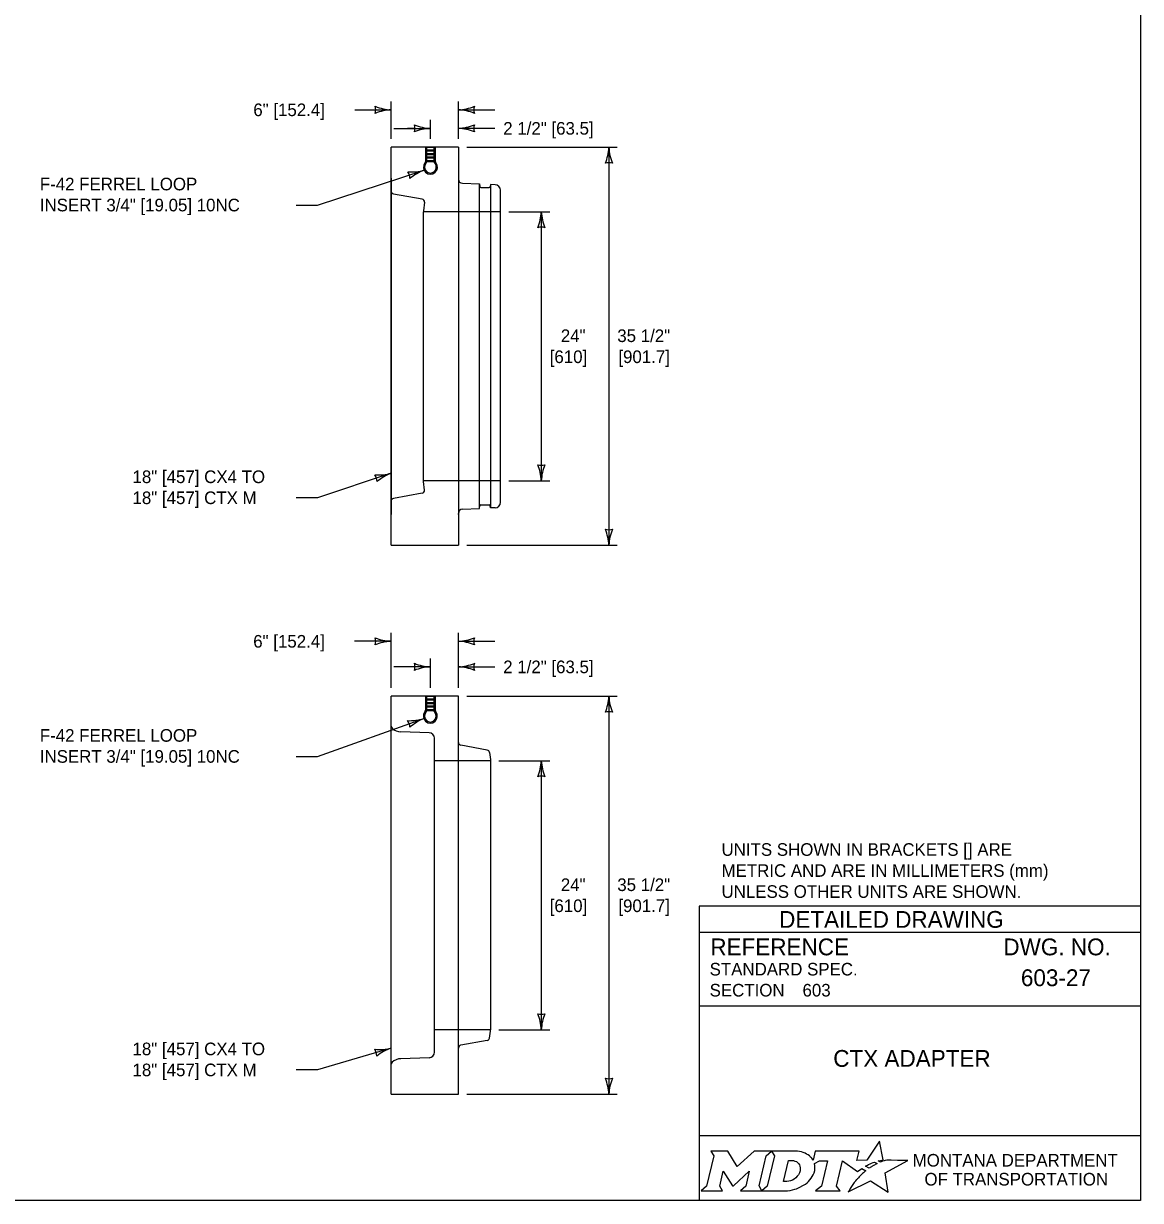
# Model space of a CAD drawing. Extents: x 49991.4 to 50021, y 49987.6 to 50011.4.
# Drawn here: x 50011.44 to 50016.75, y 49987.8 to 49993.4 of the extents above; entities that cross this region are included whole.
import ezdxf

# ---------------------------------------------------------------- set-up
doc = ezdxf.new("R2010")
doc.units = 0
for name, color, linetype in [('CONCRETE', 7, 'Continuous'), ('Default', 7, 'Continuous'), ('Level 1', 7, 'Continuous'), ('Level 2', 7, 'Continuous'), ('Level 25', 7, 'Continuous'), ('Level 3', 7, 'Continuous'), ('Level 4', 7, 'Continuous'), ('Level 5', 7, 'Continuous'), ('TEXT', 7, 'Continuous')]:
    doc.layers.add(name, color=color, linetype=linetype)

msp = doc.modelspace()

# ---------------------------------------------------------------- linework, layer by layer
at = {"layer": 'CONCRETE'}
for p, q in [((50013.1852, 49992.6637), (50013.1852, 49992.6013)), ((50013.5052, 49992.6637), (50013.5052, 49992.659)), ((50013.1852, 49991.0637), (50013.1852, 49991.1262))]:
    msp.add_line(p, q, dxfattribs=at)
at = {"layer": 'Default'}
for points in [[(50015.5126, 49987.9811), (50015.5023, 49987.9867), (50015.5139, 49987.9895), (50015.5255, 49987.9915), (50015.5081, 49988.0816), (50015.4486, 49987.9903), (50015.4013, 49987.9896), (50015.4116, 49988.0337), (50015.2024, 49988.0338), (50015.1923, 49987.9913), (50015.1865, 49987.9996)], [(50014.7056, 49988.0338), (50014.7197, 49988.0104), (50014.6862, 49987.8671), (50014.6605, 49987.8446), (50014.7621, 49987.8446), (50014.7486, 49987.8674), (50014.7648, 49987.9375), (50014.8085, 49987.8685), (50014.8138, 49987.8685), (50014.8889, 49987.938), (50014.8725, 49987.8669), (50014.8478, 49987.8449), (50014.9494, 49987.8449), (50014.9356, 49987.8682), (50014.9688, 49988.0106)], [(50014.9688, 49988.0106), (50014.9941, 49988.0338), (50014.9117, 49988.0338), (50014.8321, 49987.9608), (50014.7876, 49988.0335), (50014.7056, 49988.0338)], [(50015.1077, 49988.0338), (50014.9941, 49988.0338), (50015.0088, 49988.0109), (50014.9749, 49987.8671), (50014.9494, 49987.8449), (50015.06, 49987.8449)], [(50015.1317, 49987.9471), (50015.1305, 49987.939), (50015.1273, 49987.9297), (50015.1231, 49987.9215), (50015.1175, 49987.914), (50015.111, 49987.9071), (50015.1031, 49987.9008), (50015.0948, 49987.8961), (50015.0857, 49987.8922), (50015.0766, 49987.8899), (50015.0674, 49987.889), (50015.0515, 49987.889), (50015.0751, 49987.989), (50015.0911, 49987.989), (50015.0987, 49987.9884), (50015.1063, 49987.9865), (50015.1129, 49987.9835), (50015.119, 49987.9793), (50015.1238, 49987.9743), (50015.1275, 49987.9683), (50015.1302, 49987.9621), (50015.1318, 49987.9547), (50015.1318, 49987.9517), (50015.1317, 49987.9471)], [(50015.1991, 49987.9747), (50015.2237, 49987.9878), (50015.2606, 49987.9878), (50015.232, 49987.8673), (50015.2045, 49987.8446), (50015.3207, 49987.8446), (50015.3037, 49987.8675), (50015.3319, 49987.9877), (50015.4032, 49987.936), (50015.4243, 49987.9511), (50015.444, 49987.9402)], [(50015.3882, 49987.8843), (50015.3729, 49987.8599), (50015.3682, 49987.8524), (50015.3624, 49987.8438), (50015.3601, 49987.8395), (50015.4654, 49987.8926), (50015.5493, 49987.8375), (50015.5362, 49987.9302), (50015.6431, 49987.9886), (50015.5938, 49987.9894), (50015.5637, 49987.9898), (50015.5429, 49987.9901), (50015.5361, 49987.9886), (50015.5312, 49987.9874), (50015.5228, 49987.9851), (50015.5126, 49987.9811)], [(50015.4622, 49987.9535), (50015.4598, 49987.9518), (50015.4415, 49987.9614), (50015.4518, 49987.9671), (50015.4559, 49987.9693), (50015.4645, 49987.9733), (50015.4702, 49987.9759), (50015.4781, 49987.9789), (50015.4854, 49987.9816), (50015.4972, 49987.9742), (50015.4932, 49987.9721), (50015.4886, 49987.9696), (50015.4844, 49987.9674), (50015.4794, 49987.9645), (50015.4775, 49987.9634), (50015.4748, 49987.9618), (50015.4723, 49987.9604), (50015.47, 49987.9588), (50015.4674, 49987.957), (50015.4647, 49987.9552), (50015.4622, 49987.9535)], [(50015.1057, 49987.8522), (50015.1141, 49987.8548), (50015.1271, 49987.8602), (50015.1475, 49987.8712)], [(50015.4021, 49987.9004), (50015.4021, 49987.9004)]]:
    msp.add_lwpolyline(points, dxfattribs=at)
for centre, radius, start, end in [((50015.0868, 49987.9727), 0.1183, 300.9103, 339.1383), ((50015.1308, 49987.9554), 0.0709, 339.5329, 15.8582)]:
    msp.add_arc(centre, radius, start, end, dxfattribs=at)
for centre, major_axis, ratio, start_param, end_param in [((50015.1056, 49987.9864), (0.0834, -0.0037), 0.568097, 0.61298, 1.570796), ((50015.1612, 49987.9937), (0.0361, -0.0295), 0.469099, 1.225588, 1.570796), ((50015.4329, 49987.9305), (-0.0112, -0.0097), 0.021651, 3.157348, 6.283185), ((50015.3952, 49987.8923), (-0.00694, -0.00806), 0.008222, 0, 3.137361), ((50015.4119, 49987.9106), (-0.0098, -0.0102), 0.016458, 3.141593, 6.279097), ((50015.0603, 49987.9932), (0, 0.1484), 0.987302, 3.139398, 3.456847)]:
    msp.add_ellipse(centre, major_axis=major_axis, ratio=ratio, start_param=start_param, end_param=end_param, dxfattribs=at)
at = {"layer": 'Level 1'}
for p, q in [((50013.1852, 49990.9171), (50013.1852, 49992.8104)), ((50013.5052, 49992.8104), (50013.1852, 49992.8104)), ((50013.5052, 49992.8104), (50013.5052, 49990.9171)), ((50013.1852, 49992.6637), (50013.1852, 49991.0637)), ((50013.5246, 49992.639), (50013.605, 49992.6365)), ((50013.605, 49991.091), (50013.605, 49992.6365)), ((50013.605, 49992.6365), (50013.6073, 49992.6231)), ((50013.6583, 49992.6333), (50013.6565, 49992.6231)), ((50013.6583, 49992.6333), (50013.6583, 49991.0942)), ((50013.6794, 49992.6326), (50013.6583, 49992.6333)), ((50013.6122, 49992.619), (50013.6516, 49992.619)), ((50013.7052, 49991.1215), (50013.7052, 49992.6059)), ((50013.5052, 49991.0637), (50013.5052, 49991.0684)), ((50013.5246, 49991.0884), (50013.605, 49991.091)), ((50013.605, 49991.091), (50013.6073, 49991.1043)), ((50013.6122, 49991.1085), (50013.6516, 49991.1085)), ((50013.6583, 49991.0942), (50013.6565, 49991.1043)), ((50013.6794, 49991.0949), (50013.6583, 49991.0942)), ((50013.1852, 49990.9171), (50013.5052, 49990.9171)), ((50013.1849, 49988.3045), (50013.1849, 49990.1978)), ((50013.5049, 49990.1978), (50013.1849, 49990.1978)), ((50013.5049, 49988.3045), (50013.5049, 49990.1978)), ((50013.6422, 49989.9421), (50013.5159, 49989.9649)), ((50013.653, 49989.931), (50013.6582, 49989.8978)), ((50013.6582, 49989.8978), (50013.6582, 49989.8912)), ((50013.6582, 49989.8912), (50013.6582, 49988.6112)), ((50013.653, 49988.5713), (50013.6582, 49988.6045)), ((50013.6582, 49988.6045), (50013.6582, 49988.6112)), ((50013.6422, 49988.5603), (50013.5159, 49988.5374)), ((50013.1849, 49988.3045), (50013.5049, 49988.3045))]:
    msp.add_line(p, q, dxfattribs=at)
msp.add_lwpolyline([(49999.3835, 49998.9992), (50016.7501, 49998.9992), (50016.7501, 49987.7988), (49999.3835, 49987.7988)], close=True, dxfattribs=at)
for centre, radius, start, end in [((50013.5252, 49992.659), 0.02, 180, 268.167), ((50013.6785, 49992.6059), 0.0267, 0, 88.167), ((50013.6122, 49992.624), 0.005, 190, 270), ((50013.6516, 49992.624), 0.005, 270, 350), ((50013.6785, 49991.1215), 0.0267, 271.833, 0), ((50013.5252, 49991.0684), 0.02, 91.833, 180), ((50013.6122, 49991.1035), 0.005, 90, 170), ((50013.6516, 49991.1035), 0.005, 10, 90), ((50013.5182, 49989.978), 0.0133, 180, 259.7456), ((50013.6399, 49989.9289), 0.0133, 8.9081, 79.7456), ((50013.6399, 49988.5734), 0.0133, 280.2544, 351.0919), ((50013.5182, 49988.5243), 0.0133, 100.2544, 180)]:
    msp.add_arc(centre, radius, start, end, dxfattribs=at)
at = {"layer": 'Level 3'}
for p, q in [((50013.1852, 49992.8504), (50013.1852, 49993.0288)), ((50013.5052, 49992.8504), (50013.5052, 49993.0288)), ((50013.0118, 49992.9888), (50013.1852, 49992.9888)), ((50013.5052, 49992.9888), (50013.6786, 49992.9888)), ((50013.3719, 49992.8504), (50013.3719, 49992.9406)), ((50013.5052, 49992.8504), (50013.5052, 49992.9406)), ((50013.1984, 49992.9006), (50013.3719, 49992.9006)), ((50013.2984, 49992.9006), (50013.2637, 49992.9006)), ((50013.6786, 49992.9006), (50013.5052, 49992.9006)), ((50013.3552, 49992.8104), (50013.3885, 49992.8104)), ((50013.5452, 49992.8104), (50014.2611, 49992.8104)), ((50014.2211, 49992.8104), (50014.2211, 49990.9171)), ((50013.7452, 49992.5037), (50013.9396, 49992.5037)), ((50013.8996, 49992.5037), (50013.8996, 49991.2237)), ((50013.7452, 49991.2237), (50013.9396, 49991.2237)), ((50013.5452, 49990.9171), (50014.2611, 49990.9171)), ((50013.1849, 49990.2378), (50013.1849, 49990.4996)), ((50013.5049, 49990.2378), (50013.5049, 49990.4996)), ((50013.1849, 49990.4596), (50013.0115, 49990.4596)), ((50013.5049, 49990.4596), (50013.6783, 49990.4596)), ((50013.3716, 49990.338), (50013.1981, 49990.338)), ((50013.3716, 49990.2378), (50013.3716, 49990.378)), ((50013.5049, 49990.2378), (50013.5049, 49990.378)), ((50013.5049, 49990.338), (50013.6783, 49990.338)), ((50013.5449, 49990.1978), (50014.2611, 49990.1978)), ((50014.2211, 49990.1978), (50014.2211, 49988.3045)), ((50013.6982, 49989.8912), (50013.9396, 49989.8912)), ((50013.8996, 49989.8912), (50013.8996, 49988.6112)), ((50013.6982, 49988.6112), (50013.9396, 49988.6112)), ((50013.5449, 49988.3045), (50014.2611, 49988.3045))]:
    msp.add_line(p, q, dxfattribs=at)
for points in [[(50012.734, 49992.5356), (50012.834, 49992.5356), (50013.3419, 49992.7014)], [(50013.1852, 49991.2597), (50012.834, 49991.1426), (50012.734, 49991.1426)], [(50012.734, 49989.9118), (50012.834, 49989.9118), (50013.3403, 49990.0918)], [(50013.1849, 49988.5235), (50012.834, 49988.42), (50012.734, 49988.42)]]:
    msp.add_lwpolyline(points, dxfattribs=at)
for centre, radius, start, end in [((50013.1944, 49993.2109), 0.2223, 247.4389, 267.6225), ((50013.057, 49992.9888), 0.0548, 342.1218, 17.8441), ((50013.1966, 49992.7561), 0.233, 92.8102, 112.0601), ((50013.4938, 49993.2215), 0.233, 272.8102, 292.0601), ((50013.496, 49992.7667), 0.2223, 67.4389, 87.6225), ((50013.6334, 49992.9888), 0.0548, 162.1218, 197.8441), ((50013.3811, 49993.1227), 0.2223, 247.4389, 267.6225), ((50013.2437, 49992.9006), 0.0548, 342.1218, 17.8441), ((50013.4938, 49993.1333), 0.233, 272.8102, 292.0601), ((50013.6334, 49992.9005), 0.0548, 162.1218, 197.8441), ((50013.3833, 49992.6678), 0.233, 92.8102, 112.0601), ((50013.496, 49992.6784), 0.2223, 67.4389, 87.6225), ((50013.9989, 49992.8196), 0.2223, 337.4389, 357.6225), ((50014.4538, 49992.8218), 0.233, 182.8102, 202.0601), ((50013.2816, 49992.9154), 0.2223, 265.5377, 285.7212), ((50013.22, 49992.6616), 0.0548, 0.2205, 35.9429), ((50013.425, 49992.4837), 0.233, 110.909, 130.1588), ((50014.221, 49992.6822), 0.0548, 72.1218, 107.8441), ((50013.6775, 49992.513), 0.2223, 337.4389, 357.6225), ((50014.1323, 49992.5152), 0.233, 182.8102, 202.0601), ((50013.8995, 49992.3755), 0.0548, 72.1218, 107.8441), ((50013.8996, 49991.3519), 0.0548, 252.1218, 287.8441), ((50013.6669, 49991.2123), 0.233, 2.8102, 22.0601), ((50014.1217, 49991.2145), 0.2223, 157.4389, 177.6225), ((50013.1236, 49991.4733), 0.2223, 265.908, 286.0916), ((50013.0636, 49991.2191), 0.0548, 0.5909, 36.3132), ((50013.2698, 49991.0425), 0.233, 111.2793, 130.5292), ((50014.2211, 49991.0453), 0.0548, 252.1218, 287.8441), ((50013.9884, 49990.9057), 0.233, 2.8102, 22.0601), ((50014.4432, 49990.9079), 0.2223, 157.4389, 177.6225), ((50013.1941, 49990.6818), 0.2223, 247.4389, 267.6225), ((50013.0567, 49990.4597), 0.0548, 342.1218, 17.8441), ((50013.1963, 49990.2269), 0.233, 92.8102, 112.0601), ((50013.4935, 49990.6923), 0.233, 272.8102, 292.0601), ((50013.4957, 49990.2375), 0.2223, 67.4389, 87.6225), ((50013.6331, 49990.4596), 0.0548, 162.1218, 197.8441), ((50013.3808, 49990.5602), 0.2223, 247.4389, 267.6225), ((50013.2434, 49990.3381), 0.0548, 342.1218, 17.8441), ((50013.383, 49990.1053), 0.233, 92.8102, 112.0601), ((50013.4935, 49990.5707), 0.233, 272.8102, 292.0601), ((50013.4957, 49990.1159), 0.2223, 67.4389, 87.6225), ((50013.6331, 49990.338), 0.0548, 162.1218, 197.8441), ((50013.9989, 49990.207), 0.2223, 337.4389, 357.6225), ((50014.4538, 49990.2092), 0.233, 182.8102, 202.0601), ((50014.221, 49990.0696), 0.0548, 72.1218, 107.8441), ((50013.2745, 49990.3042), 0.2223, 267.0303, 287.2139), ((50013.2195, 49990.0489), 0.0548, 1.7132, 37.4355), ((50013.4291, 49989.8764), 0.233, 112.4016, 131.6515), ((50013.6775, 49989.9004), 0.2223, 337.4389, 357.6225), ((50014.1323, 49989.9026), 0.233, 182.8102, 202.0601), ((50013.8995, 49989.763), 0.0548, 72.1218, 107.8441), ((50013.8996, 49988.7394), 0.0548, 252.1218, 287.8441), ((50013.6669, 49988.5998), 0.233, 2.8102, 22.0601), ((50014.1217, 49988.602), 0.2223, 157.4389, 177.6225), ((50013.1309, 49988.7391), 0.2223, 263.883, 284.0665), ((50013.0619, 49988.4872), 0.0548, 358.5658, 34.2882), ((50013.2617, 49988.3035), 0.233, 109.2543, 128.5041), ((50014.2211, 49988.4327), 0.0548, 252.1218, 287.8441), ((50013.9884, 49988.2931), 0.233, 2.8102, 22.0601), ((50014.4432, 49988.2953), 0.2223, 157.4389, 177.6225)]:
    msp.add_arc(centre, radius, start, end, dxfattribs=at)
at = {"layer": 'Level 4'}
for p, q in [((50013.3497, 49992.748), (50013.3497, 49992.8104)), ((50013.3552, 49992.748), (50013.3552, 49992.8104)), ((50013.3552, 49992.7983), (50013.3885, 49992.7983)), ((50013.3885, 49992.8104), (50013.3885, 49992.748)), ((50013.3941, 49992.8104), (50013.3941, 49992.748)), ((50013.348, 49992.7405), (50013.3485, 49992.7418)), ((50013.3531, 49992.7385), (50013.3536, 49992.7397)), ((50013.3547, 49992.7433), (50013.389, 49992.7433)), ((50013.3552, 49992.7936), (50013.3885, 49992.7936)), ((50013.3552, 49992.7815), (50013.3885, 49992.7815)), ((50013.3552, 49992.7768), (50013.3885, 49992.7768)), ((50013.3552, 49992.7648), (50013.3885, 49992.7648)), ((50013.3552, 49992.7601), (50013.3885, 49992.7601)), ((50013.3552, 49992.748), (50013.3885, 49992.748)), ((50013.3906, 49992.7385), (50013.3901, 49992.7397)), ((50013.3958, 49992.7405), (50013.3953, 49992.7418)), ((50013.3328, 49992.5634), (50013.1962, 49992.5882)), ((50013.3436, 49992.5487), (50013.3385, 49992.5079)), ((50013.3385, 49992.5079), (50013.3385, 49992.5037)), ((50013.3385, 49991.2237), (50013.3385, 49992.5037)), ((50013.7052, 49992.5037), (50013.3385, 49992.5037)), ((50013.3385, 49991.2196), (50013.3385, 49991.2237)), ((50013.7052, 49991.2237), (50013.3385, 49991.2237)), ((50013.3436, 49991.1788), (50013.3385, 49991.2196)), ((50013.3328, 49991.164), (50013.1962, 49991.1393)), ((50013.3494, 49990.1354), (50013.3494, 49990.1978)), ((50013.3549, 49990.1354), (50013.3549, 49990.1978)), ((50013.3549, 49990.1857), (50013.3882, 49990.1857)), ((50013.3549, 49990.181), (50013.3882, 49990.181)), ((50013.3549, 49990.169), (50013.3882, 49990.169)), ((50013.3549, 49990.1643), (50013.3882, 49990.1643)), ((50013.3882, 49990.1978), (50013.3882, 49990.1354)), ((50013.3938, 49990.1978), (50013.3938, 49990.1354)), ((50013.3477, 49990.128), (50013.3482, 49990.1292)), ((50013.3528, 49990.1259), (50013.3533, 49990.1272)), ((50013.3544, 49990.1307), (50013.3887, 49990.1307)), ((50013.3549, 49990.1522), (50013.3882, 49990.1522)), ((50013.3549, 49990.1475), (50013.3882, 49990.1475)), ((50013.3549, 49990.1354), (50013.3882, 49990.1354)), ((50013.3903, 49990.1259), (50013.3898, 49990.1272)), ((50013.3955, 49990.128), (50013.395, 49990.1292)), ((50013.3658, 49990.0246), (50013.2316, 49990.0289)), ((50013.3916, 49988.5044), (50013.3916, 49989.998)), ((50013.6582, 49989.8912), (50013.3916, 49989.8912)), ((50013.6582, 49988.6112), (50013.3916, 49988.6112)), ((50013.3658, 49988.4777), (50013.2316, 49988.4734))]:
    msp.add_line(p, q, dxfattribs=at)
for centre, radius, start, end in [((50013.3325, 49992.7467), 0.0167, 321.9927, 338.1986), ((50013.333, 49992.748), 0.0167, 338.1986, 0), ((50013.333, 49992.748), 0.0222, 338.1986, 0), ((50013.4108, 49992.748), 0.0222, 180, 201.8014), ((50013.4108, 49992.748), 0.0167, 180, 201.8014), ((50013.4113, 49992.7467), 0.0167, 201.8014, 218.0073), ((50013.3719, 49992.7159), 0.0333, 141.9927, 38.0073), ((50013.3719, 49992.7159), 0.0278, 141.9927, 38.0073), ((50013.3325, 49992.7467), 0.0222, 321.9927, 338.1986), ((50013.4113, 49992.7467), 0.0222, 201.8014, 218.0073), ((50013.1985, 49992.6013), 0.0133, 180, 259.7498), ((50013.3304, 49992.5503), 0.0133, 352.875, 79.7498), ((50013.3304, 49991.1771), 0.0133, 280.2502, 7.125), ((50013.1985, 49991.1262), 0.0133, 100.2502, 180), ((50013.3716, 49990.1034), 0.0333, 141.9927, 38.0073), ((50013.3716, 49990.1034), 0.0278, 141.9927, 38.0073), ((50013.3322, 49990.1342), 0.0167, 321.9927, 338.1986), ((50013.3327, 49990.1354), 0.0167, 338.1986, 0), ((50013.3322, 49990.1342), 0.0222, 321.9927, 338.1986), ((50013.3327, 49990.1354), 0.0222, 338.1986, 0), ((50013.4105, 49990.1354), 0.0222, 180, 201.8014), ((50013.411, 49990.1342), 0.0222, 201.8014, 218.0073), ((50013.4105, 49990.1354), 0.0167, 180, 201.8014), ((50013.411, 49990.1342), 0.0167, 201.8014, 218.0073), ((50013.1982, 49990.0557), 0.0133, 180, 228.319), ((50013.2337, 49990.0956), 0.0667, 228.319, 268.167), ((50013.3649, 49989.998), 0.0267, 0, 88.167), ((50013.3649, 49988.5044), 0.0267, 271.833, 0), ((50013.1982, 49988.4466), 0.0133, 131.681, 180), ((50013.2337, 49988.4068), 0.0667, 91.833, 131.681)]:
    msp.add_arc(centre, radius, start, end, dxfattribs=at)
at = {"layer": 'Level 5'}
for p, q in [((50016.7501, 49989.1988), (50014.6501, 49989.1988)), ((50014.6501, 49989.1988), (50014.6501, 49987.7988)), ((50016.7501, 49989.0738), (50014.6501, 49989.0738)), ((50016.3862, 49988.8587), (50016.3862, 49988.8587)), ((50015.1444, 49988.7993), (50015.1444, 49988.7993)), ((50016.7501, 49988.7238), (50014.6501, 49988.7238)), ((50015.7001, 49988.4747), (50015.7001, 49988.4747)), ((50016.7501, 49988.1057), (50014.6501, 49988.1057))]:
    msp.add_line(p, q, dxfattribs=at)
at = {"layer": 'TEXT'}
for p, q in [((50013.3497, 49992.8104), (50013.3941, 49992.8104)), ((50013.3494, 49990.1978), (50013.3938, 49990.1978))]:
    msp.add_line(p, q, dxfattribs=at)

# ---------------------------------------------------------------- texts
at = {"layer": 'Default'}
for s, p in [('MONTANA DEPARTMENT', (50015.6663, 49987.96)), ('OF TRANSPORTATION', (50015.7225, 49987.87))]:
    msp.add_text(s, height=0.06, dxfattribs=at).set_placement(p)
at = {"layer": 'Level 2'}
for s, p in [('6" [152.4]', (50012.5293, 49992.9588)), ('2 1/2" [63.5]', (50013.7186, 49992.8706)), ('F-42 FERREL LOOP', (50011.5137, 49992.6056)), ('INSERT 3/4" [19.05] 10NC', (50011.5137, 49992.5056)), ('35 1/2"', (50014.2611, 49991.8837)), ('[901.7]', (50014.2661, 49991.7837)), ('18" [457] CX4 TO ', (50011.9547, 49991.2126)), ('18" [457] CTX M', (50011.9547, 49991.1126)), ('6" [152.4]', (50012.529, 49990.4296)), ('2 1/2" [63.5]', (50013.7183, 49990.308)), ('F-42 FERREL LOOP', (50011.5137, 49989.9818)), ('INSERT 3/4" [19.05] 10NC', (50011.5137, 49989.8818)), ('35 1/2"', (50014.2611, 49989.2712)), ('[901.7]', (50014.2661, 49989.1712)), ('18" [457] CX4 TO ', (50011.9547, 49988.49)), ('18" [457] CTX M', (50011.9547, 49988.39))]:
    msp.add_text(s, height=0.06, dxfattribs=at).set_placement(p)
for s, p in [('24"', (50013.9925, 49991.8837)), ('[610]', (50013.9396, 49991.7837)), ('UNITS SHOWN IN BRACKETS [] ARE ', (50014.757, 49989.4388)), ('METRIC AND ARE IN MILLIMETERS (mm) ', (50014.757, 49989.3388)), ('24"', (50013.9925, 49989.2712)), ('UNLESS OTHER UNITS ARE SHOWN.', (50014.757, 49989.2388)), ('[610]', (50013.9396, 49989.1712))]:
    msp.add_text(s, height=0.06, rotation=360, dxfattribs=at).set_placement(p)
at = {"layer": 'Level 25'}
for s, height, p in [('603-27', 0.08, (50016.1813, 49988.8187)), ('603', 0.06, (50015.1423, 49988.7693)), ('CTX ADAPTER', 0.08, (50015.2885, 49988.4347))]:
    msp.add_text(s, height=height, dxfattribs=at).set_placement(p)
at = {"layer": 'Level 5'}
for s, height, p in [('DETAILED DRAWING', 0.0799, (50015.0311, 49989.0963)), ('REFERENCE', 0.08, (50014.7037, 49988.9654)), ('DWG. NO.', 0.08, (50016.0979, 49988.9654)), ('STANDARD SPEC.', 0.06, (50014.7004, 49988.8694)), ('SECTION', 0.06, (50014.7004, 49988.7694))]:
    msp.add_text(s, height=height, dxfattribs=at).set_placement(p)

doc.saveas('drawing.dxf')
